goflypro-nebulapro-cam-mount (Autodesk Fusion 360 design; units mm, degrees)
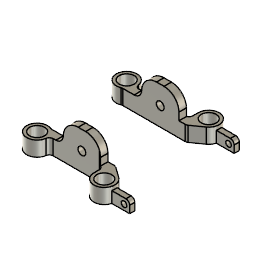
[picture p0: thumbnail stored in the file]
sketch "Skizze1" plane through (0, 0, 0) normal (0, 0, 1) x axis (1, 0, 0)
  line L1 (8.5, 2.5) -> (-8.739, 2.5)
  line L2 (7.2, 0.5) -> (-7.245, 0.5)
  line L3 (7.2, 0.5) -> (7.2, -2)
  line L4 (8.739, 0.5) -> (7.2, 0.5)
  line L5 (11.6215, 0.2827) -> (8.5, 2.5)
  line L6 (-3.5, 2.5) -> (-3.5, 0.5)
  line L7 (6.5, 2.5) -> (6.5, 0.5)
  line L8 (17.5, -1.3) -> (12.7111, -1.3)
  line L9 (17.5, -2.7) -> (17.5, -1.3)
  line L10 (12.7111, -2.7) -> (17.5, -2.7)
  circle C1 centre (-10, 0) radius 2
  circle C2 centre (10, -2) radius 2
  circle C3 centre (-10, 0) radius 2.8
  circle C4 centre (10, -2) radius 2.8
  circle C5 centre (-10, 24) radius 2
  point P7 (7.2, -2)
  point P9 (-7.245, 0.5)
  point P10 (-8.739, 2.5)
  point P11 (8.739, 0.5)
  point P13 (11.6215, 0.2827)
  point P14 (-3.5, 0.5)
  point P15 (-3.5, 2.5)
  point P16 (6.5, 0.5)
  point P17 (6.5, 2.5)
  point P20 (12.7111, -1.3)
  point P21 (12.7111, -2.7)
  concentric C1 C3
  concentric C2 C4
  horizontal L1
  coincident C4 P7
  tangent C4 L3
  perpendicular L2 L3
  coincident C3 P9
  coincident C3 P10
  coincident C4 P11
  perpendicular L3 L4
  coincident C4 P13
  tangent C4 L5
  coincident L2 P14
  coincident L1 P15
  perpendicular L1 L6
  coincident L2 P16
  coincident L1 P17
  perpendicular L1 L7
  horizontal L10
  horizontal L8
  vertical L9
  coincident C4 P20
  coincident C4 P21
  dimension "d1" diameter C1 = 4
  dimension "d2" diameter C2 = 4
  dimension "d3" diameter C3 = 5.6
  dimension "d4" diameter C4 = 5.6
  dimension "d27" diameter C5 = 4
extrude "Extrusion1" new body sketch "Skizze1" profile of C1 C2 C3 C4 L1 L2 L3 L4 L5 L6 L7 along normal blind 4 bodies "GoFlyPro - NebulaPro cam mount - left"
extrude "Extrusion5" add sketch "Skizze1" profile of L1 L2 L6 L7 along normal blind 10
sketch "Skizze2" plane through (0, 2.5, 0) normal (0, 1, 0) x axis (1, 0, 0)
  line L1 (-7.3847, 0) -> (10, 0)
  line L2 (10, 0) -> (10, -6)
  line L3 (10, -6) -> (-7.3847, -6)
  line L4 (-7.3847, -6) -> (-7.3847, 0)
  line L5 (-8.0404, 0) -> (10, 0)
  line L6 (-8.0404, -8) -> (-8.0404, 0)
  line L7 (10, -8) -> (-8.0404, -8)
  line L8 (10, 0) -> (10, -8)
  line L9 (-8.739, 0) -> (8.5, 0)
  line L10 (-8.739, -4) -> (-8.739, 0)
  line L11 (-3.5, -4) -> (-8.739, -4)
  line L12 (-3.5, -10) -> (-3.5, -4)
  line L13 (6.5, -10) -> (-3.5, -10)
  line L14 (6.5, -4) -> (6.5, -10)
  line L15 (8.5, -4) -> (6.5, -4)
  line L16 (8.5, 0) -> (8.5, -4)
  circle C1 centre (1.5, -5) radius 1.05
  dimension "d8" diameter C1 = 2.1
extrude "Extrusion2" cut sketch "Skizze2" profile of C1 against normal blind 4
extrude "Extrusion6" add sketch "Skizze1" profile of C4 L8 L9 L10 along normal blind 3
sketch "Skizze3" plane through (0, -2.7, 0) normal (0, -1, 0) x axis (1, 0, 0)
  line L1 (17.5, 0) -> (12.7111, 0)
  line L2 (17.5, 3) -> (17.5, 0)
  line L3 (12.7111, 3) -> (17.5, 3)
  line L4 (12.7111, 0) -> (12.7111, 3)
  circle C1 centre (16, 1.5) radius 0.75
  dimension "d43" diameter C1 = 1.5
extrude "Extrusion7" cut sketch "Skizze3" profile of C1 against normal blind 2
fillet "Abrundung11" radius 4
fillet "Abrundung12" radius 2
fillet "Abrundung13" radius 1
fillet "Abrundung14" radius 1
work_plane "Arbeitsebene" AlongDistance 12
mirror "Spiegeln" mirrorStitchTolerance 0.1 bodies "GoFlyPro - NebulaPro cam mount - right"
named bodies: "GoFlyPro - NebulaPro cam mount - left", "GoFlyPro - NebulaPro cam mount - right"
